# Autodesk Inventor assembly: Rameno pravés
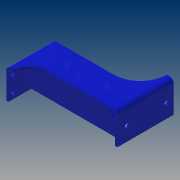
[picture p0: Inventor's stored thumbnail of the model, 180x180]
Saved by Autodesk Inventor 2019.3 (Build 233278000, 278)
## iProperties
Created: 2019-02
Part Number: Rameno pravés
Material: Všeobecné
Document SubType Name: Assembly
Designer: B-hon
Author: B-hon
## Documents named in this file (3)
- C:\Users\B-hon\OneDrive\Plocha\Bakalářka22\Deska střední\Rameno pravés.iam
- C:\Users\B-hon\OneDrive\Plocha\Bakalářka22\Deska střední\Rameno pravés.ipt
- C:\Users\B-hon\OneDrive\Plocha\Bakalářka22\Deska střední\Výztuha ramene s.ipt
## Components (2 placed, 2 different names)
1. Rameno pravés:1 — Proti sobě:1, Proti sobě:2, Stejný směr:1
2. Výztuha ramene s:1 — Proti sobě:1, Proti sobě:2, Stejný směr:1
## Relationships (3: Mate 2, Flush 1)
- Proti sobě:1 [Mate]: Rameno pravés:1 ↔ Výztuha ramene s:1
- Proti sobě:2 [Mate]: Rameno pravés:1 ↔ Výztuha ramene s:1
- Stejný směr:1 [Flush]: Rameno pravés:1 ↔ Výztuha ramene s:1
